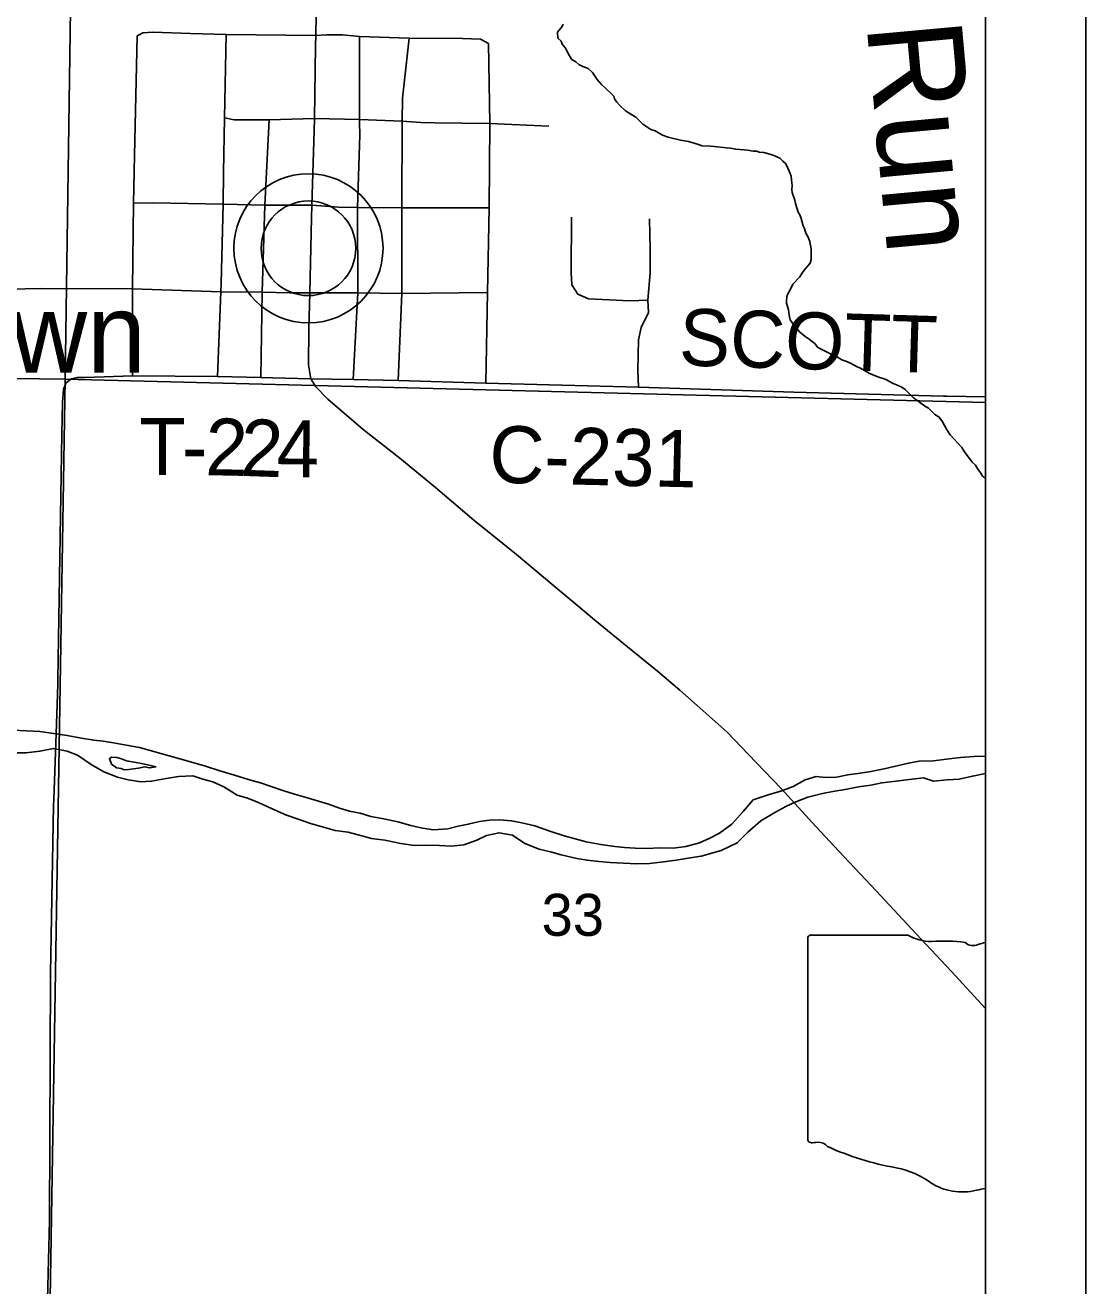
# Model space of a CAD drawing. Extents: x 0 to 34, y 0 to 22.
# Drawn here: x 7.942 to 9, y 17.741 to 18.998 of the extents above; entities that cross this region are included whole.
import ezdxf

# ---------------------------------------------------------------- set-up
doc = ezdxf.new("R2010")
doc.units = 0
for name, color, linetype in [('Default', 7, 'Continuous'), ('GM_X_County_Road', 7, 'Continuous'), ('GM_X_County_Road_Text', 7, 'Continuous'), ('GM_X_Major_River', 7, 'Continuous'), ('GM_X_Minor_River', 7, 'Continuous'), ('GM_X_Minor_River_Text', 7, 'Continuous'), ('GM_X_Section', 7, 'Continuous'), ('GM_X_Section_Text', 7, 'Continuous'), ('GM_X_State_Location', 7, 'Continuous'), ('GM_X_State_Route', 7, 'Continuous'), ('GM_X_Township_Road', 7, 'Continuous'), ('GM_X_Township_Road_Text', 7, 'Continuous'), ('GM_X_Unincorporated', 7, 'Continuous'), ('GM_X_Unincorporated_Location', 7, 'Continuous'), ('GM_X_Unincorporated_Text', 7, 'Continuous'), ('SH_Data', 7, 'Continuous')]:
    doc.layers.add(name, color=color, linetype=linetype)

msp = doc.modelspace()

# ---------------------------------------------------------------- linework, layer by layer
at = {"layer": 'Default'}
for points in [[(8.9, 17.6104), (8.9, 20.9), (6.0871, 20.9), (6.0839, 20.7194), (6.0809, 20.5156), (6.08, 20.4768), (6.0777, 20.3704), (6.0696, 20.0002), (6.0632, 19.7108), (6.0568, 19.5343), (5.9893, 17.6676), (6.9889, 17.643), (7.0308, 17.6406), (8.0065, 17.6245)], [(8.9, 18.6218), (8.9, 19.6382), (7.9969, 19.6588), (7.9821, 18.6451)], [(8.9, 17.6038), (8.9, 18.6218), (7.9821, 18.6451), (7.9657, 17.6264), (8.0077, 17.6258)]]:
    msp.add_lwpolyline(points, close=True, dxfattribs=at)
at = {"layer": 'GM_X_County_Road'}
msp.add_line((8.8613, 18.6282), (8.9, 18.6274), dxfattribs=at)
for points in [[(7.8928, 18.7341), (7.9585, 18.7356), (8.0495, 18.735), (8.1373, 18.7323), (8.1786, 18.7317), (8.2063, 18.7311), (8.2261, 18.7313)], [(8.2272, 18.6455), (8.2693, 18.6449), (8.3142, 18.6439), (8.4017, 18.641), (8.5539, 18.6372), (8.709, 18.632), (8.858, 18.6282), (8.8613, 18.6282)]]:
    msp.add_lwpolyline(points, dxfattribs=at)
at = {"layer": 'GM_X_Major_River'}
for points in [[(8.5165, 18.1811), (8.5018, 18.1836), (8.4908, 18.1868), (8.4799, 18.1897), (8.4656, 18.1945), (8.4505, 18.1997), (8.4376, 18.2026), (8.4274, 18.2047), (8.4153, 18.2056), (8.4054, 18.2054), (8.3955, 18.2041), (8.3841, 18.2013), (8.3742, 18.1992), (8.3639, 18.1967), (8.3494, 18.1958), (8.3385, 18.1975), (8.3268, 18.2), (8.3139, 18.2036), (8.2999, 18.2065), (8.2871, 18.2091), (8.2765, 18.2123), (8.2659, 18.2144), (8.2557, 18.2172), (8.2448, 18.2212), (8.235, 18.2244), (8.2248, 18.2272), (8.2108, 18.2313), (8.2003, 18.2345), (8.1867, 18.2393), (8.1769, 18.2425), (8.1659, 18.2454), (8.1512, 18.2502), (8.1365, 18.2546), (8.1222, 18.2591), (8.1071, 18.2635), (8.0565, 18.2777), (8.0451, 18.2798), (8.0304, 18.2823), (8.0201, 18.284), (8.0107, 18.285), (7.9986, 18.2871), (7.9842, 18.2896), (7.957, 18.2939), (7.9437, 18.2945), (7.93, 18.2951)], [(7.9277, 18.2724), (7.9429, 18.2725), (7.957, 18.2741), (7.9707, 18.2769), (7.9843, 18.274), (7.9945, 18.27), (8.0083, 18.2607), (8.0207, 18.2536), (8.0343, 18.2481), (8.0449, 18.2456), (8.0577, 18.2435), (8.0684, 18.2441), (8.0828, 18.2468), (8.0954, 18.2489), (8.1095, 18.2494), (8.1196, 18.2462), (8.1295, 18.2434), (8.1404, 18.2386), (8.1539, 18.2304), (8.1641, 18.2272), (8.175, 18.2228), (8.1885, 18.2165), (8.2028, 18.2102), (8.2157, 18.2061), (8.227, 18.2021), (8.2376, 18.1989), (8.2515, 18.1949), (8.2644, 18.1935), (8.278, 18.1898)], [(8.0728, 18.2584), (8.066, 18.26), (8.0566, 18.2621), (8.0509, 18.263), (8.0433, 18.2646), (8.0384, 18.2666), (8.0339, 18.2678), (8.0286, 18.2683), (8.0263, 18.2668), (8.0285, 18.2611), (8.0333, 18.2576)], [(8.9, 18.2692), (8.8885, 18.2687), (8.8752, 18.2678), (8.8638, 18.2665), (8.8482, 18.2645), (8.8338, 18.2643), (8.8231, 18.2622), (8.809, 18.2587), (8.7988, 18.2566), (8.7858, 18.2538), (8.7751, 18.2521), (8.7626, 18.2504), (8.7515, 18.2483), (8.7405, 18.2478), (8.7311, 18.2487), (8.72, 18.2455), (8.7081, 18.2388), (8.697, 18.2345), (8.6833, 18.2305), (8.6684, 18.2255), (8.6583, 18.2139), (8.6471, 18.2012), (8.6348, 18.1923), (8.6244, 18.1871), (8.6149, 18.1828), (8.6011, 18.1792), (8.589, 18.1775), (8.5757, 18.1777), (8.562, 18.1772), (8.5506, 18.1774), (8.54, 18.178), (8.5305, 18.1789), (8.5165, 18.1811)], [(8.0333, 18.2576), (8.0382, 18.2567), (8.0409, 18.2556), (8.0458, 18.2558), (8.0504, 18.2565), (8.0553, 18.2572), (8.0618, 18.2586), (8.0663, 18.2574), (8.0728, 18.2584)], [(8.278, 18.1898), (8.2878, 18.187), (8.3011, 18.1853), (8.3169, 18.1819), (8.3306, 18.1802), (8.3412, 18.1804), (8.3556, 18.1801), (8.3674, 18.1795), (8.3799, 18.1808), (8.3929, 18.1855), (8.4025, 18.1899), (8.415, 18.1927), (8.4283, 18.1902), (8.4407, 18.182), (8.455, 18.1765), (8.4663, 18.1736), (8.4769, 18.1708), (8.4924, 18.1671), (8.5026, 18.1654), (8.5147, 18.164), (8.5257, 18.1631), (8.5522, 18.1618), (8.5648, 18.162), (8.5788, 18.1636), (8.5914, 18.1653), (8.6055, 18.1677), (8.6165, 18.1694), (8.6364, 18.1752), (8.6524, 18.1828), (8.6629, 18.1933), (8.676, 18.2045), (8.6898, 18.2129), (8.7009, 18.2188), (8.7109, 18.2236), (8.7227, 18.2283), (8.7376, 18.2319), (8.7479, 18.234), (8.76, 18.236), (8.7734, 18.2384), (8.7855, 18.2401), (8.7966, 18.2426), (8.811, 18.2442), (8.824, 18.2459), (8.8381, 18.2476), (8.8482, 18.2443), (8.8619, 18.2456), (8.8737, 18.2462), (8.887, 18.2493), (8.9, 18.2519)]]:
    msp.add_lwpolyline(points, dxfattribs=at)
at = {"layer": 'GM_X_Minor_River'}
for points in [[(8.7567, 18.6644), (8.7499, 18.6687), (8.7454, 18.6704), (8.7353, 18.6752), (8.7326, 18.6771), (8.7297, 18.6806), (8.7274, 18.6822), (8.7241, 18.6849), (8.7203, 18.6877), (8.7144, 18.6924), (8.7114, 18.6963), (8.7092, 18.6986), (8.7051, 18.7044), (8.7044, 18.7071), (8.7038, 18.7116), (8.7035, 18.7143), (8.7028, 18.7166), (8.7017, 18.7208), (8.7014, 18.7239), (8.7023, 18.7288), (8.7039, 18.7318), (8.7067, 18.7374), (8.7079, 18.7397), (8.7149, 18.7471), (8.7168, 18.7504), (8.7192, 18.7538), (8.7231, 18.7583), (8.7251, 18.7609), (8.7263, 18.7643), (8.7262, 18.7749), (8.7258, 18.7772), (8.7251, 18.7802), (8.7248, 18.7825), (8.7227, 18.7875), (8.7208, 18.7906), (8.7194, 18.7952), (8.7183, 18.7979), (8.7162, 18.8052), (8.7148, 18.809), (8.7133, 18.8117), (8.7105, 18.8201), (8.7098, 18.8235), (8.7073, 18.8312), (8.707, 18.8339), (8.7071, 18.8384), (8.7068, 18.8407), (8.7062, 18.8476), (8.7051, 18.8503), (8.7018, 18.8579), (8.7004, 18.8602), (8.6978, 18.8626), (8.6948, 18.8653), (8.6888, 18.8681), (8.685, 18.8694), (8.679, 18.871), (8.6744, 18.8715), (8.6718, 18.8723), (8.6683, 18.8724), (8.6627, 18.8733), (8.6592, 18.8738), (8.6509, 18.8744), (8.6456, 18.8753), (8.6418, 18.8758), (8.6293, 18.8772), (8.6259, 18.8773), (8.6171, 18.8779), (8.6149, 18.8787), (8.6096, 18.8804), (8.6039, 18.882), (8.596, 18.8834), (8.5861, 18.8859), (8.5835, 18.8863), (8.5778, 18.8884), (8.5707, 18.8927), (8.5662, 18.894), (8.5583, 18.8995), (8.5512, 18.9065), (8.5479, 18.9085), (8.5411, 18.9128), (8.5352, 18.9179), (8.5322, 18.9214), (8.53, 18.9245), (8.5293, 18.9272), (8.5267, 18.9299), (8.517, 18.9389), (8.5129, 18.9439), (8.5082, 18.9509), (8.5037, 18.9548), (8.4984, 18.9568), (8.4946, 18.9588), (8.4913, 18.9615), (8.4875, 18.9639), (8.485, 18.9674), (8.4824, 18.9724), (8.481, 18.9751), (8.478, 18.979), (8.4769, 18.982), (8.4736, 18.9852), (8.4733, 18.9912), (8.4777, 18.9968), (8.4789, 18.9991)], [(8.9, 18.5463), (8.897, 18.5485), (8.8955, 18.5512), (8.8922, 18.5554), (8.89, 18.5593), (8.8867, 18.5624), (8.8789, 18.5725), (8.8763, 18.5771), (8.8648, 18.5895), (8.8612, 18.5953), (8.8572, 18.6026), (8.8539, 18.6073), (8.8494, 18.61), (8.843, 18.6163), (8.8393, 18.6186), (8.8281, 18.6265), (8.8243, 18.6304), (8.8199, 18.6347), (8.8165, 18.6371), (8.8135, 18.6383), (8.8071, 18.6411), (8.8048, 18.6423), (8.8007, 18.6447), (8.7981, 18.6459), (8.7943, 18.6467), (8.7853, 18.6504), (8.7811, 18.6528), (8.7755, 18.6559), (8.7721, 18.6575), (8.7654, 18.6611), (8.7608, 18.6631), (8.7567, 18.6644)]]:
    msp.add_lwpolyline(points, dxfattribs=at)
at = {"layer": 'GM_X_Section'}
for points in [[(6.9929, 19.6861), (7.9969, 19.6588), (7.9821, 18.6451), (7.008, 18.6577)], [(7.008, 18.6577), (7.9821, 18.6451), (7.9657, 17.6264), (7.0384, 17.6474), (7.0009, 17.6487)]]:
    msp.add_lwpolyline(points, close=True, dxfattribs=at)
at = {"layer": 'GM_X_State_Route'}
for points in [[(8.232, 18.9775), (8.2322, 18.9878), (8.2332, 19.0483), (8.2351, 19.1022), (8.2345, 19.1255), (8.2326, 19.1447), (8.2293, 19.1698), (8.2242, 19.2057), (8.2189, 19.2423)], [(8.2272, 18.6455), (8.2248, 18.6595), (8.2251, 18.6949), (8.2261, 18.7313), (8.228, 18.8061), (8.2282, 18.8186), (8.2306, 18.8927), (8.2308, 18.905), (8.232, 18.9775)], [(8.9, 18.0175), (8.9, 18.0175), (8.8659, 18.0547), (8.8261, 18.0968), (8.7909, 18.1349), (8.7588, 18.1691), (8.7308, 18.1991), (8.6961, 18.2368), (8.6637, 18.2708), (8.6423, 18.2931), (8.6126, 18.3196), (8.5952, 18.3348), (8.5728, 18.3539), (8.543, 18.3781), (8.5121, 18.4034), (8.4895, 18.4224), (8.4676, 18.4406), (8.4324, 18.4701), (8.3899, 18.5045), (8.3514, 18.5371), (8.3159, 18.5664), (8.2793, 18.5949), (8.2442, 18.6252), (8.2323, 18.6375), (8.2272, 18.6455)]]:
    msp.add_lwpolyline(points, dxfattribs=at)
at = {"layer": 'GM_X_Township_Road'}
msp.add_line((8.1429, 18.9887), (8.2322, 18.9878), dxfattribs=at)
for points in [[(8.0495, 18.735), (8.0505, 18.8207), (8.0513, 18.8682), (8.0541, 18.9873)], [(8.0541, 18.9873), (8.0597, 18.9905), (8.0697, 18.9912), (8.1073, 18.9899), (8.1429, 18.9887)], [(8.1429, 18.9887), (8.141, 18.9058), (8.1401, 18.8512), (8.1397, 18.8196), (8.1377, 18.7409), (8.1373, 18.7323), (8.134, 18.6478)], [(8.2322, 18.9878), (8.2426, 18.9883), (8.2587, 18.9883), (8.2757, 18.9869), (8.3251, 18.9851), (8.3785, 18.9847), (8.3963, 18.9841), (8.4045, 18.9799)], [(8.2757, 18.9869), (8.2757, 18.9039), (8.2758, 18.9011)], [(8.3142, 18.6439), (8.3179, 18.7306), (8.3179, 18.816), (8.3184, 18.9022), (8.3187, 18.9253), (8.3251, 18.9851)], [(8.4045, 18.9799), (8.4058, 18.9001), (8.4052, 18.8158), (8.4035, 18.7314), (8.4017, 18.641)], [(8.4645, 18.8973), (8.4058, 18.9001), (8.3509, 18.9006), (8.3369, 18.9011), (8.3184, 18.9022), (8.2757, 18.9039), (8.2308, 18.905), (8.1857, 18.9038), (8.1506, 18.9038), (8.141, 18.9058)], [(8.1772, 18.6466), (8.1786, 18.7317), (8.1812, 18.8185), (8.1857, 18.9038)], [(8.2758, 18.9011), (8.2761, 18.8888), (8.2739, 18.8162), (8.274, 18.7313), (8.2693, 18.6449)], [(8.4052, 18.8158), (8.3179, 18.816), (8.2739, 18.8162), (8.2548, 18.8167), (8.2282, 18.8186), (8.1812, 18.8185), (8.1397, 18.8196), (8.0695, 18.8208), (8.0505, 18.8207)], [(8.5634, 18.724), (8.5454, 18.7231), (8.5041, 18.7252), (8.4933, 18.73), (8.4876, 18.739), (8.4867, 18.7516), (8.487, 18.8067)], [(8.5539, 18.6372), (8.5532, 18.6536), (8.5541, 18.6842), (8.5565, 18.6965), (8.564, 18.7114), (8.5634, 18.724), (8.5655, 18.751), (8.5655, 18.7743), (8.5649, 18.8049)], [(7.9749, 18.3457), (7.9789, 18.5903), (7.9794, 18.622), (7.9805, 18.6348), (7.9829, 18.641), (7.9883, 18.6454), (7.9943, 18.6466), (8.002, 18.6468), (8.0492, 18.6483), (8.0495, 18.735)], [(8.2261, 18.7313), (8.274, 18.7313), (8.3179, 18.7306), (8.4035, 18.7314)], [(8.0492, 18.6483), (8.134, 18.6478), (8.1772, 18.6466), (8.2013, 18.6461), (8.2272, 18.6455)], [(7.9708, 18.2258), (7.9731, 18.2917), (7.9748, 18.3407), (7.9749, 18.3457)], [(7.9669, 17.6364), (7.963, 17.6433), (7.9627, 17.6556), (7.9635, 17.677), (7.9647, 17.7272), (7.9666, 17.8059), (7.9676, 18.0527), (7.9705, 18.2198), (7.9708, 18.2258)]]:
    msp.add_lwpolyline(points, dxfattribs=at)
at = {"layer": 'GM_X_Unincorporated'}
for radius in [0.0744, 0.0472]:
    msp.add_circle((8.2248, 18.7756), radius, dxfattribs=at)
at = {"layer": 'GM_X_Unincorporated_Location'}
msp.add_line((8.2248, 18.7756), (8.2248, 18.7756), dxfattribs=at)
at = {"layer": 'GM_X_Unincorporated_Text'}
for p, q in [((8.8225, 18.0908), (8.7259, 18.0908)), ((8.7227, 18.0873), (8.7227, 17.8872)), ((8.9, 17.8381), (8.9, 18.0832))]:
    msp.add_line(p, q, dxfattribs=at)
for centre, major_axis, start_param, end_param in [((8.7265, 18.0878), (0.00382, 0), 1.727492, 3.291633), ((8.8455, 18.114), (0.037, 0), 4.042888, 4.731792), ((8.8577, 17.9784), (0.133, 0), 1.404758, 1.657859), ((8.8879, 18.0888), (0.0107, 0), 3.836095, 5.185415), ((8.9036, 18.0657), (0.0222, 0), 1.733576, 2.079405), ((8.7265, 17.8868), (0.00385, 0), 2.993084, 4.5083), ((8.7271, 17.9072), (0.0294, 0), 4.665946, 4.897461), ((8.7331, 17.8757), (0.0106, 0), 0.519207, 1.627899), ((8.8669, 18.0555), (0.2524, 0), 4.195997, 4.488961), ((8.7917, 17.7973), (0.079, 0), 0.823519, 1.323587), ((8.8771, 17.8747), (0.0501, 0), 4.026481, 4.996735), ((8.9061, 17.8055), (0.0412, 0), 1.718319, 1.94098)]:
    msp.add_ellipse(centre, major_axis=major_axis, ratio=0.8, start_param=start_param, end_param=end_param, dxfattribs=at)
at = {"layer": 'SH_Data'}
for p, q in [((9, 21), (9, 14)), ((8.9, 20.9), (8.9, 14.1))]:
    msp.add_line(p, q, dxfattribs=at)

# ---------------------------------------------------------------- texts
at = {"layer": 'GM_X_County_Road_Text'}
for s, rotation, p in [('SCOTT', 358.277, (8.5939, 18.6589)), ('C-231', 358.6366, (8.4047, 18.542))]:
    msp.add_text(s, height=0.05682, rotation=rotation, dxfattribs=at).set_placement(p)
at = {"layer": 'GM_X_Minor_River_Text'}
msp.add_text('Run', height=0.09467, rotation=275.1983, dxfattribs=at).set_placement((8.7813, 18.9988))
at = {"layer": 'GM_X_Section_Text'}
msp.add_text('33', height=0.04186, rotation=0, dxfattribs=at).set_placement((8.4573, 18.09))
at = {"layer": 'GM_X_State_Location'}
for s in ['s', 'r']:
    msp.add_text(s, height=0.000189, dxfattribs=at).set_placement((8.8838, 17.974))
msp.add_text('177', height=0.000189, rotation=0, dxfattribs=at).set_placement((8.8169, 17.9602))
at = {"layer": 'GM_X_Township_Road_Text'}
for s, rotation, p in [('T', 359.9657, (8.0561, 18.5496)), ('2', 358.777, (8.1216, 18.5494)), ('2', 358.0065, (8.1564, 18.5487)), ('4', 359.4534, (8.1929, 18.5475)), ('-', 359.6331, (8.0985, 18.5496))]:
    msp.add_text(s, height=0.0568, rotation=rotation, dxfattribs=at).set_placement(p)
at = {"layer": 'GM_X_Unincorporated_Text'}
msp.add_text('Darrtown', height=0.07898, rotation=0, dxfattribs=at).set_placement((7.6344, 18.6515))

doc.saveas('drawing.dxf')
